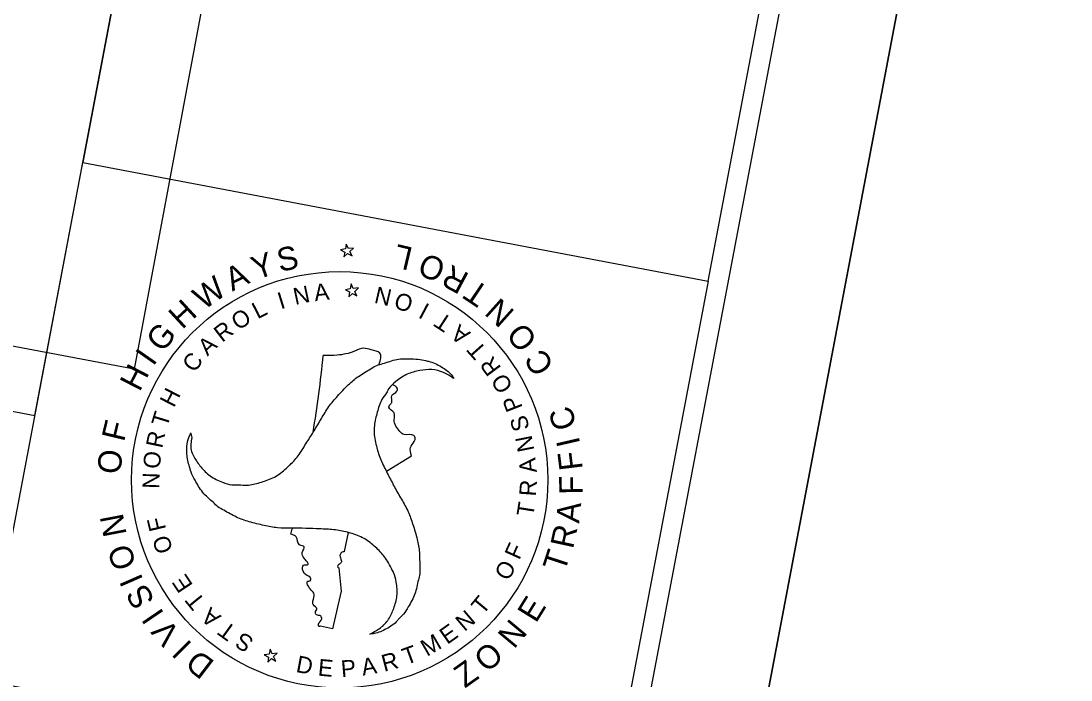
# Model space of a CAD drawing. Extents: x 1615680 to 1617075, y 898420 to 901168.
# Drawn here: x 1616848.5 to 1617075.3, y 900621.1 to 900763.4 of the extents above; entities that cross this region are included whole.
import ezdxf

# ---------------------------------------------------------------- set-up
doc = ezdxf.new("R2010")
doc.units = 0
for name, color, linetype in [('DEV BORDER CELL', 7, 'Continuous'), ('DEV DOT SWIRL SEAL CELL', 7, 'Continuous'), ('Sheet Clip Boundary CELL', 7, 'Continuous'), ('Sheet Plan CELL', 7, 'Continuous'), ('Sheet Plot Border Outside CELL', 7, 'Continuous'), ('Text', 7, 'Continuous')]:
    doc.layers.add(name, color=color, linetype=linetype)

msp = doc.modelspace()

# ---------------------------------------------------------------- linework, layer by layer
at = {"layer": 'DEV BORDER CELL'}
for points in [[(1616014.55, 901139.21), (1615734.74, 899665.53), (1616766.32, 899469.67), (1617046.12, 900943.35)], [(1616905.88, 900964.73), (1616861.86, 900732.87), (1616996.95, 900707.23), (1617040.97, 900939.08)], [(1616840.59, 900620.87), (1616861.86, 900732.87), (1616996.95, 900707.23), (1616975.68, 900595.22)]]:
    msp.add_lwpolyline(points, close=True, dxfattribs=at)
at = {"layer": 'DEV DOT SWIRL SEAL CELL'}
for p, q in [((1616918.56, 900714.19), (1616917.51, 900714.02)), ((1616917.51, 900714.02), (1616918.44, 900713.51)), ((1616918.44, 900713.51), (1616918.23, 900712.45)), ((1616918.23, 900712.45), (1616919.03, 900713.2)), ((1616918.77, 900715.25), (1616918.56, 900714.19)), ((1616919.23, 900714.26), (1616918.77, 900715.25)), ((1616919.03, 900713.2), (1616920, 900712.69)), ((1616920.32, 900714.39), (1616919.23, 900714.26)), ((1616919.52, 900713.63), (1616920.32, 900714.39)), ((1616920, 900712.69), (1616919.52, 900713.63)), ((1616919.82, 900706.62), (1616919.62, 900705.56)), ((1616920.28, 900705.64), (1616919.82, 900706.62)), ((1616919.62, 900705.56), (1616918.56, 900705.39)), ((1616918.56, 900705.39), (1616919.49, 900704.89)), ((1616919.49, 900704.89), (1616919.29, 900703.83)), ((1616919.29, 900703.83), (1616920.08, 900704.57)), ((1616920.08, 900704.57), (1616921.05, 900704.06)), ((1616921.37, 900705.76), (1616920.28, 900705.64)), ((1616920.58, 900705.01), (1616921.37, 900705.76)), ((1616921.05, 900704.06), (1616920.58, 900705.01)), ((1616927.43, 900666.17), (1616932.82, 900669.53)), ((1616918.41, 900648.8), (1616919.23, 900652.93)), ((1616917.17, 900645.27), (1616917.66, 900640.28)), ((1616917.66, 900640.28), (1616915.79, 900632.1)), ((1616915.79, 900632.1), (1616913.19, 900632.68)), ((1616902.31, 900627.74), (1616902.1, 900626.67)), ((1616902.77, 900626.75), (1616902.31, 900627.74)), ((1616903.86, 900626.87), (1616902.77, 900626.75)), ((1616903.06, 900626.12), (1616903.86, 900626.87)), ((1616902.1, 900626.67), (1616901.05, 900626.51)), ((1616901.05, 900626.51), (1616901.98, 900626)), ((1616901.98, 900626), (1616901.78, 900624.94)), ((1616901.78, 900624.94), (1616902.57, 900625.69)), ((1616902.57, 900625.69), (1616903.54, 900625.18)), ((1616903.54, 900625.18), (1616903.06, 900626.12))]:
    msp.add_line(p, q, dxfattribs=at)
for start, end in [(350.4529, 354.5729), (344.9279, 345.2256)]:
    msp.add_arc((1616681.63, 900713.24), 233.19, start, end, dxfattribs=at)
for points in [[(1616925.85, 900689.2), (1616926.01, 900691.68), (1616924.16, 900692.4), (1616922.56, 900692.74), (1616920.51, 900692.09), (1616916.81, 900691.24), (1616913.77, 900691.18)], [(1616885.09, 900674.44), (1616885.15, 900674.35), (1616885.14, 900671.73), (1616885.9, 900669.21), (1616887.35, 900667.1), (1616889.36, 900665.16), (1616892, 900663.79), (1616894.06, 900663.26), (1616895.09, 900663.25), (1616896.88, 900663.16), (1616898.33, 900663.29), (1616901.12, 900664.05), (1616903.92, 900665.29), (1616906.42, 900667.39), (1616906.62, 900667.57), (1616908.56, 900669.82), (1616910.25, 900672.43), (1616911.82, 900674.91), (1616913.38, 900677.54), (1616915.02, 900680.12), (1616916.87, 900682.4), (1616919.19, 900684.83), (1616921.43, 900686.67), (1616924.06, 900688.3), (1616925.37, 900689.03), (1616926.65, 900689.42), (1616929.69, 900690.32), (1616932.83, 900690.43), (1616934.72, 900690.32), (1616936.29, 900689.97), (1616936.55, 900689.92), (1616939.3, 900688.71), (1616941.48, 900686.96), (1616942.02, 900686.2)], [(1616942.02, 900686.2), (1616939.76, 900687.51), (1616937.22, 900688.12), (1616934.64, 900687.9), (1616931.95, 900687.13), (1616929.47, 900685.55), (1616927.98, 900684.03), (1616927.45, 900683.12), (1616926.46, 900681.67), (1616925.87, 900680.28), (1616925.1, 900677.53), (1616924.79, 900674.45), (1616925.36, 900671.25), (1616925.42, 900670.99), (1616926.44, 900668.18), (1616927.8, 900665.43), (1616929.16, 900662.79), (1616930.68, 900660.13), (1616932.13, 900657.42), (1616933.14, 900654.69), (1616934.09, 900651.45), (1616934.55, 900648.6), (1616934.65, 900645.52), (1616934.64, 900643.99), (1616934.34, 900642.71), (1616933.59, 900639.66), (1616932.13, 900636.85), (1616931.1, 900635.29), (1616929.97, 900634.12), (1616929.8, 900633.9), (1616927.41, 900632.12), (1616924.81, 900631.11), (1616923.83, 900630.99)], [(1616932.82, 900669.53), (1616932.64, 900671.29), (1616933.43, 900672.58), (1616933.66, 900673.23), (1616933.35, 900673.86), (1616931.24, 900674.09), (1616930.36, 900674.75), (1616929.12, 900677.31), (1616929.08, 900678.76), (1616927.99, 900680.03), (1616928.1, 900680.44), (1616928.58, 900681.01), (1616928.57, 900682.48), (1616929.71, 900683.44), (1616929.78, 900684.12), (1616928.83, 900684.85)], [(1616923.83, 900630.99), (1616926.14, 900632.33), (1616927.91, 900634.21), (1616929.01, 900636.54), (1616929.7, 900639.28), (1616929.57, 900642.22), (1616928.98, 900644.28), (1616928.5, 900645.19), (1616927.68, 900646.76), (1616926.81, 900647.94), (1616924.8, 900650.02), (1616922.29, 900651.8), (1616919.26, 900652.93), (1616919, 900653), (1616916.04, 900653.54), (1616912.98, 900653.71), (1616910.03, 900653.83), (1616906.95, 900653.87), (1616903.91, 900653.96), (1616901.02, 900654.45), (1616897.76, 900655.26), (1616895.03, 900656.27), (1616892.3, 900657.74), (1616891.02, 900658.51), (1616890.04, 900659.4), (1616887.76, 900661.61), (1616886.08, 900664.25), (1616885.25, 900665.94), (1616884.78, 900667.48), (1616884.69, 900667.74), (1616884.32, 900670.71), (1616884.74, 900673.47), (1616885.15, 900674.35)], [(1616913.19, 900632.68), (1616912.93, 900632.64), (1616912.74, 900633.14), (1616913.47, 900634.27), (1616913.06, 900634.98), (1616912.52, 900635.05), (1616912.09, 900635.65), (1616912.42, 900636.45), (1616911.61, 900637.38), (1616911.55, 900638.11), (1616911.83, 900639.58), (1616910.41, 900641.66), (1616910.44, 900642.4), (1616910.95, 900642.51), (1616911.12, 900642.94), (1616909.82, 900643.99), (1616909.66, 900644.22), (1616909.36, 900645.66), (1616909.71, 900645.97), (1616910.37, 900645.96), (1616910.51, 900646.13), (1616910.29, 900646.63), (1616909.63, 900647.39), (1616909.26, 900648.61), (1616909.67, 900649.86), (1616908.65, 900650.28), (1616907.94, 900651.97), (1616907.39, 900652.39), (1616906.79, 900652.59)], [(1616918.41, 900648.8), (1616917.71, 900648.59), (1616917.39, 900647.96), (1616917.69, 900646.95), (1616917.54, 900646.29), (1616916.84, 900645.65), (1616917.17, 900645.27)]]:
    msp.add_spline(points, degree=3, dxfattribs=at)
at = {"layer": 'Sheet Clip Boundary CELL'}
for points in [[(1616176.29, 901060.7), (1616848.46, 900914.27), (1616896.28, 900812.91), (1616872.94, 900688.21), (1616835.87, 900695.21), (1616753.94, 900262.18), (1616898.09, 900233.43), (1616734.79, 899562.1), (1616202.98, 899609.43), (1616198.71, 899647.14), (1615822.69, 899825.07), (1616054.34, 901080.76)], [(1616176.29, 901060.7), (1616914, 900899.99), (1616896.28, 900812.91), (1616872.94, 900688.21), (1616835.87, 900695.21), (1616753.94, 900262.18), (1616898.09, 900233.43), (1616747.89, 899480.25), (1615915.8, 899646.19), (1615751.76, 899738.03), (1615981.58, 900932.46), (1616145.94, 900899.57)]]:
    msp.add_lwpolyline(points, close=True, dxfattribs=at)
at = {"layer": 'Sheet Plan CELL'}
msp.add_lwpolyline([(1616859.19, 900973.59), (1616804.79, 900687.04), (1616851.47, 900678.18), (1616905.88, 900964.73)], close=True, dxfattribs=at)
at = {"layer": 'Sheet Plot Border Outside CELL'}
for points in [[(1616760.47, 899304.87), (1615679.78, 899510.06), (1615994.65, 901168.43), (1617075.34, 900963.24)], [(1616760.47, 899304.87), (1617075.34, 900963.24), (1615994.65, 901168.43), (1615679.78, 899510.06)]]:
    msp.add_lwpolyline(points, close=True, dxfattribs=at)
at = {"layer": 'Text'}
msp.add_circle((1616917.34, 900664.32), 44.97, dxfattribs=at)

# ---------------------------------------------------------------- texts
at = {"layer": 'DEV DOT SWIRL SEAL CELL'}
for s, height, rotation, p in [('Y', 5.04, 18.9977, (1616899.33, 900707.45)), ('S', 5.04, 12.4743, (1616904.4, 900709.18)), ('W', 5.04, 35.0626, (1616887.96, 900700.86)), ('A', 5.04, 26.0256, (1616894.13, 900704.96)), ('A', 3.63, 7.0227, (1616912.01, 900702.88)), ('I', 3.63, 17.1788, (1616904.59, 900701.12)), ('N', 3.63, 12.1007, (1616907.73, 900702.07)), ('N', 3.63, 166.9823, (1616928.85, 900705.33)), ('O', 3.63, 162.1763, (1616933.52, 900703.81)), ('H', 5.04, 42.7126, (1616883.29, 900696.66)), ('L', 3.63, 27.335, (1616899.6, 900698.96)), ('I', 3.63, 152.0201, (1616937.01, 900702.05)), ('O', 3.63, 32.4131, (1616895.39, 900696.49)), ('T', 3.63, 146.942, (1616941.93, 900699.08)), ('G', 5.04, 50.7661, (1616879.02, 900691.62)), ('R', 3.63, 37.4912, (1616891.93, 900693.88)), ('A', 3.63, 141.8639, (1616945.78, 900696.08)), ('A', 3.63, 42.5693, (1616888.77, 900690.92)), ('T', 3.63, 131.7077, (1616949.3, 900692.41)), ('I', 5.04, 55.0534, (1616877.05, 900688.7)), ('C', 3.63, 52.7254, (1616885.92, 900687.29)), ('R', 3.63, 126.6297, (1616952.37, 900688.51)), ('H', 5.04, 62.7034, (1616874.1, 900683.16)), ('O', 3.63, 121.5516, (1616954.91, 900684.44)), ('H', 3.63, 62.8816, (1616881.51, 900679.75)), ('P', 3.63, 111.3954, (1616956.93, 900679.91)), ('F', 5.04, 76.5069, (1616870.74, 900672.37)), ('S', 3.63, 106.3173, (1616958.42, 900675.42)), ('R', 3.63, 78.1158, (1616878.97, 900670.99)), ('N', 3.63, 101.2392, (1616959.44, 900670.73)), ('O', 5.04, 85.0143, (1616869.99, 900665.43)), ('O', 3.63, 83.1939, (1616878.41, 900666.54)), ('A', 3.63, 96.1611, (1616959.95, 900665.98)), ('N', 3.63, 88.272, (1616878.34, 900662.34)), ('R', 3.63, 86.005, (1616959.73, 900660.67)), ('T', 3.63, 80.9269, (1616959.13, 900656.22)), ('N', 5.04, 100.8354, (1616871.34, 900652.55)), ('F', 3.63, 103.5063, (1616879.87, 900653.68)), ('O', 3.63, 108.5844, (1616881.39, 900649.11)), ('O', 5.04, 109.3428, (1616873.51, 900645.92)), ('F', 3.63, 65.6926, (1616956.13, 900646.85)), ('O', 3.63, 60.6146, (1616953.76, 900642.29)), ('I', 5.04, 113.6302, (1616874.97, 900642.72)), ('E', 3.63, 123.8186, (1616885.75, 900641.55)), ('S', 5.04, 119.8342, (1616877.51, 900638.3)), ('T', 3.63, 128.8967, (1616888.47, 900638.12)), ('T', 3.63, 50.4584, (1616948.28, 900634.98)), ('I', 5.04, 124.1215, (1616879.53, 900635.42)), ('A', 3.63, 139.0529, (1616891.9, 900634.86)), ('N', 3.63, 40.3022, (1616944.31, 900631.41)), ('V', 5.04, 130.83, (1616883.1, 900631.23)), ('T', 3.63, 144.1309, (1616895.27, 900632.25)), ('E', 3.63, 35.2241, (1616940.57, 900628.64)), ('I', 5.04, 135.1173, (1616885.64, 900628.79)), ('S', 3.63, 149.209, (1616899.04, 900629.92)), ('M', 3.63, 30.146, (1616936.19, 900626.07)), ('D', 5.04, 142.7084, (1616890.54, 900624.96)), ('R', 3.63, 14.9118, (1616926.93, 900622.84)), ('T', 3.63, 19.9899, (1616931.68, 900624.26)), ('D', 3.63, 349.5214, (1616907.73, 900622.83)), ('E', 3.63, 354.5995, (1616912.53, 900622.04)), ('P', 3.63, 4.7556, (1616917.75, 900621.66)), ('A', 3.63, 9.8337, (1616922.36, 900622.01))]:
    msp.add_text(s, height=height, rotation=rotation, dxfattribs=at).set_placement(p)
at = {"layer": 'Text'}
for s, height, rotation, p in [('L', 5.04, 166.6784, (1616933.41, 900714.4)), ('O', 5.04, 158.239, (1616940.59, 900711.5)), ('R', 5.04, 152.0012, (1616945.58, 900708.69)), ('T', 5.04, 146.1304, (1616949.97, 900705.57)), ('N', 5.04, 138.1413, (1616955.38, 900700.64)), ('O', 5.04, 129.702, (1616960.3, 900694.66)), ('C', 5.04, 122.3301, (1616963.84, 900688.9)), ('T', 3.63, 73.0378, (1616880.06, 900675.5)), ('C', 5.04, 107.2527, (1616968.63, 900675.95)), ('I', 5.04, 102.9996, (1616969.35, 900672.12)), ('F', 5.04, 97.012, (1616969.88, 900666.65)), ('F', 5.04, 91.0244, (1616969.84, 900661.16)), ('A', 5.04, 84.0528, (1616969.07, 900654.81)), ('R', 5.04, 77.815, (1616967.73, 900649.24)), ('T', 5.04, 71.9442, (1616965.92, 900644.17)), ('E', 5.04, 58.201, (1616959.74, 900633.2)), ('N', 5.04, 50.212, (1616955.01, 900627.61)), ('O', 5.04, 41.7727, (1616949.21, 900622.48)), ('Z', 5.04, 35.4181, (1616944.38, 900619.21))]:
    msp.add_text(s, height=height, rotation=rotation, dxfattribs=at).set_placement(p)

doc.saveas('drawing.dxf')
